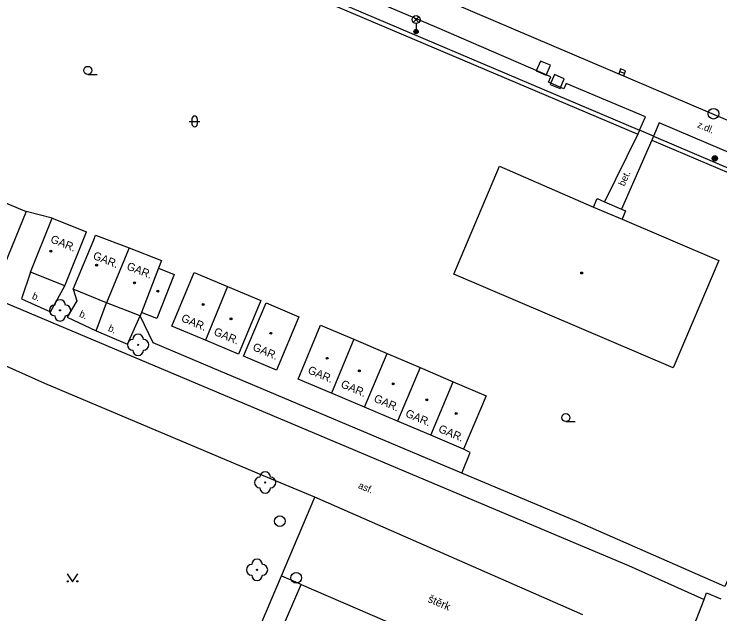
# Model space of a CAD drawing. Extents: x -596024 to -594475, y -1163820 to -1161957.
# Drawn here: x -594676 to -594609.9, y -1162309.5 to -1162253.3 of the extents above; entities that cross this region are included whole.
import ezdxf

# ---------------------------------------------------------------- set-up
doc = ezdxf.new("R2010")
doc.units = 0
for name, color, linetype in [('Level 10', 7, 'Continuous'), ('Level 11', 7, 'Continuous'), ('Level 22', 7, 'Continuous'), ('Level 25', 7, 'Continuous'), ('Level 26', 7, 'Continuous'), ('Level 27', 7, 'Continuous'), ('Level 33', 7, 'Continuous'), ('Level 36', 7, 'Continuous'), ('Level 39', 7, 'Continuous'), ('Level 40', 7, 'Continuous'), ('Level 41', 7, 'Continuous'), ('Level 5', 7, 'Continuous'), ('Level 7', 7, 'Continuous'), ('Level 8', 7, 'Continuous')]:
    doc.layers.add(name, color=color, linetype=linetype)

msp = doc.modelspace()

# ---------------------------------------------------------------- linework, layer by layer
at = {"layer": 'Level 10'}
for points in [[(-594662.38, -1162240.56), (-594636.69, -1162251.47), (-594598.02, -1162268)], [(-594682.8, -1162283.58), (-594684.03, -1162283.03), (-594686.08, -1162282.17), (-594689.66, -1162280.67), (-594687.61, -1162275.8), (-594659.66, -1162287.58)], [(-594673.15, -1162287.88), (-594682.8, -1162283.58)], [(-594652.66, -1162296.52), (-594673.15, -1162287.88)], [(-594659.66, -1162287.58), (-594623.99, -1162302.61)], [(-594647.87, -1162298.54), (-594652.66, -1162296.52)], [(-594622.76, -1162309.54), (-594647.87, -1162298.54)], [(-594623.99, -1162302.61), (-594618.49, -1162304.91), (-594611.41, -1162308.1)], [(-594611.41, -1162308.1), (-594611.18, -1162307.5), (-594609.84, -1162308.04)]]:
    msp.add_lwpolyline(points, dxfattribs=at)
at = {"layer": 'Level 11'}
for points in [[(-594625.75, -1162259.17), (-594636.44, -1162254.53), (-594664.44, -1162242.64)], [(-594625.96, -1162259.66), (-594625.75, -1162259.17)], [(-594624.53, -1162260.27), (-594625.96, -1162259.66)], [(-594624.32, -1162259.78), (-594624.53, -1162260.27)], [(-594617.44, -1162264.16), (-594616.88, -1162262.92), (-594624.32, -1162259.78)], [(-594615.6, -1162263.46), (-594616.13, -1162264.72)], [(-594598.68, -1162270.76), (-594599.02, -1162270.52), (-594615.6, -1162263.46)], [(-594617.44, -1162264.16), (-594617.62, -1162264.53)], [(-594617.62, -1162264.53), (-594620.73, -1162270.86)], [(-594616.13, -1162264.72), (-594616.29, -1162265.09)], [(-594616.29, -1162265.09), (-594619.13, -1162271.56)], [(-594621.76, -1162271.36), (-594621.42, -1162270.56), (-594620.73, -1162270.86)], [(-594620.73, -1162270.86), (-594619.13, -1162271.56)], [(-594619.13, -1162271.56), (-594618.77, -1162271.72), (-594619.09, -1162272.48)], [(-594674.48, -1162277.46), (-594675.34, -1162279.94), (-594672.62, -1162281.16), (-594671.27, -1162278.74)], [(-594670.49, -1162279.04), (-594670.15, -1162280.14), (-594671.04, -1162281.66), (-594668.34, -1162282.94)], [(-594668.34, -1162282.94), (-594667.38, -1162280.33)], [(-594668.34, -1162282.94), (-594665.4, -1162284.2), (-594664.22, -1162281.54)], [(-594650.98, -1162305.9), (-594647.87, -1162298.54)], [(-594613.33, -1162313.08), (-594611.41, -1162308.1)]]:
    msp.add_lwpolyline(points, dxfattribs=at)
at = {"layer": 'Level 22'}
for centre in [(-594671.72, -1162281.03), (-594664.41, -1162284.26), (-594652.51, -1162297.15), (-594653.27, -1162305.33)]:
    msp.add_circle(centre, 0.05, dxfattribs=at)
for centre, start, end in [((-594671.72, -1162280.53), 0, 180), ((-594672.22, -1162281.03), 90, 270), ((-594671.22, -1162281.03), 270, 90), ((-594671.72, -1162281.53), 180, 0), ((-594664.41, -1162283.76), 0, 180), ((-594664.91, -1162284.26), 90, 270), ((-594663.91, -1162284.26), 270, 90), ((-594664.41, -1162284.76), 180, 0), ((-594652.51, -1162296.65), 0, 180), ((-594653.01, -1162297.15), 90, 270), ((-594652.01, -1162297.15), 270, 90), ((-594652.51, -1162297.65), 180, 0), ((-594653.27, -1162304.83), 0, 180), ((-594653.77, -1162305.33), 90, 270), ((-594652.77, -1162305.33), 270, 90), ((-594653.27, -1162305.83), 180, 0)]:
    msp.add_arc(centre, 0.5, start, end, dxfattribs=at)
at = {"layer": 'Level 25'}
for radius in [0.25, 0.2, 0.15, 0.1, 0.05]:
    msp.add_circle((-594610.4, -1162266.8), radius, dxfattribs=at)
at = {"layer": 'Level 26'}
for points in [[(-594625.802, -1162258.081), (-594626.719, -1162257.682), (-594627.118, -1162258.599), (-594626.201, -1162258.998)], [(-594624.504, -1162259.335), (-594625.425, -1162258.944), (-594625.815, -1162259.865), (-594624.895, -1162260.256)]]:
    msp.add_lwpolyline(points, close=True, dxfattribs=at)
at = {"layer": 'Level 27'}
msp.add_line((-594619.314, -1162258.651), (-594618.846, -1162258.829), dxfattribs=at)
msp.add_lwpolyline([(-594619.402, -1162258.885), (-594618.935, -1162259.062), (-594618.758, -1162258.595), (-594619.225, -1162258.418)], close=True, dxfattribs=at)
for centre in [(-594610.52, -1162262.61), (-594651.14, -1162300.77), (-594649.6, -1162306.08)]:
    msp.add_circle(centre, 0.5, dxfattribs=at)
at = {"layer": 'Level 33'}
for p, q in [((-594638.645, -1162254.06), (-594638.115, -1162253.53)), ((-594638.645, -1162253.53), (-594638.115, -1162254.06)), ((-594638.38, -1162254.17), (-594638.38, -1162254.92))]:
    msp.add_line(p, q, dxfattribs=at)
for centre, radius in [((-594638.38, -1162253.795), 0.375), ((-594638.38, -1162254.92), 0.2), ((-594638.38, -1162254.92), 0.145), ((-594638.38, -1162254.92), 0.0876)]:
    msp.add_circle(centre, radius, dxfattribs=at)
at = {"layer": 'Level 36'}
for p, q in [((-594669.12, -1162258.925), (-594668.245, -1162258.925)), ((-594659.616, -1162263.336), (-594658.616, -1162263.336)), ((-594659.366, -1162263.086), (-594659.366, -1162263.586)), ((-594658.866, -1162263.086), (-594658.866, -1162263.586)), ((-594624.35, -1162291.445), (-594623.475, -1162291.445))]:
    msp.add_line(p, q, dxfattribs=at)
msp.add_lwpolyline([(-594671.05, -1162305.71), (-594670.55, -1162306.46), (-594670.05, -1162305.71)], dxfattribs=at)
for centre, radius in [((-594669.12, -1162258.55), 0.375), ((-594624.35, -1162291.07), 0.375), ((-594671, -1162306.41), 0.05), ((-594670.101, -1162306.41), 0.05)]:
    msp.add_circle(centre, radius, dxfattribs=at)
for centre, start, end in [((-594659.116, -1162263.086), 0, 180), ((-594659.116, -1162263.586), 180, 0)]:
    msp.add_arc(centre, 0.25, start, end, dxfattribs=at)
at = {"layer": 'Level 39'}
for centre, radius in [((-594672.59, -1162275.49), 0.09), ((-594672.59, -1162275.49), 0.0398), ((-594668.29, -1162276.8), 0.09), ((-594668.29, -1162276.8), 0.0398), ((-594622.87, -1162277.53), 0.09), ((-594622.87, -1162277.53), 0.0398), ((-594664.75, -1162278.45), 0.09), ((-594664.75, -1162278.45), 0.0398), ((-594662.57, -1162279.24), 0.09), ((-594662.57, -1162279.24), 0.0398), ((-594658.32, -1162280.49), 0.09), ((-594658.32, -1162280.49), 0.0398), ((-594655.71, -1162281.82), 0.09), ((-594655.71, -1162281.82), 0.0398), ((-594651.97, -1162283.18), 0.09), ((-594651.97, -1162283.18), 0.0398), ((-594646.71, -1162285.52), 0.09), ((-594646.71, -1162285.52), 0.0398), ((-594643.69, -1162286.69), 0.09), ((-594643.69, -1162286.69), 0.0398), ((-594640.51, -1162287.9), 0.09), ((-594640.51, -1162287.9), 0.0398), ((-594637.38, -1162289.41), 0.09), ((-594637.38, -1162289.41), 0.0398), ((-594634.62, -1162290.7), 0.09), ((-594634.62, -1162290.7), 0.0398)]:
    msp.add_circle(centre, radius, dxfattribs=at)
at = {"layer": 'Level 5'}
for points in [[(-594634.84, -1162277.63), (-594630.55, -1162267.51)], [(-594630.55, -1162267.51), (-594621.76, -1162271.36)], [(-594677.98, -1162270.5), (-594674.89, -1162271.76)], [(-594621.76, -1162271.36), (-594619.09, -1162272.48)], [(-594674.89, -1162271.76), (-594676.96, -1162276.82)], [(-594674.48, -1162277.46), (-594672.46, -1162272.38)], [(-594672.46, -1162272.38), (-594669.25, -1162273.66)], [(-594619.09, -1162272.48), (-594610.01, -1162276.35)], [(-594671.27, -1162278.74), (-594669.25, -1162273.66)], [(-594670.49, -1162279.04), (-594668.57, -1162274.42), (-594668.4, -1162274)], [(-594668.4, -1162274), (-594665.24, -1162275.18)], [(-594665.24, -1162275.18), (-594667.38, -1162280.33)], [(-594665.24, -1162275.18), (-594662.23, -1162276.35)], [(-594662.23, -1162276.35), (-594662.51, -1162277.08)], [(-594610.01, -1162276.35), (-594614.29, -1162286.42)], [(-594671.27, -1162278.74), (-594674.48, -1162277.46)], [(-594662.51, -1162277.08), (-594664.1, -1162281.24)], [(-594662.51, -1162277.08), (-594661.04, -1162277.66)], [(-594661.04, -1162277.66), (-594662.67, -1162281.8)], [(-594661.24, -1162282.51), (-594659.15, -1162277.48)], [(-594659.15, -1162277.48), (-594656.04, -1162278.79)], [(-594614.29, -1162286.42), (-594634.84, -1162277.63)], [(-594656.04, -1162278.79), (-594658.11, -1162283.82)], [(-594656.04, -1162278.79), (-594652.93, -1162280.1)], [(-594667.38, -1162280.33), (-594670.49, -1162279.04)], [(-594652.93, -1162280.1), (-594655.02, -1162285.12)], [(-594664.22, -1162281.54), (-594667.38, -1162280.33)], [(-594654.55, -1162285.31), (-594652.43, -1162280.31)], [(-594652.43, -1162280.31), (-594649.37, -1162281.65)], [(-594664.1, -1162281.24), (-594664.22, -1162281.54)], [(-594662.67, -1162281.8), (-594664.1, -1162281.24)], [(-594649.37, -1162281.65), (-594651.46, -1162286.62)], [(-594658.11, -1162283.82), (-594661.24, -1162282.51)], [(-594649.42, -1162287.48), (-594647.33, -1162282.42)], [(-594647.33, -1162282.42), (-594644.21, -1162283.74)], [(-594655.02, -1162285.12), (-594658.11, -1162283.82)], [(-594644.21, -1162283.74), (-594646.31, -1162288.8)], [(-594644.21, -1162283.74), (-594641.09, -1162285.07)], [(-594651.46, -1162286.62), (-594654.55, -1162285.31)], [(-594643.21, -1162290.11), (-594641.09, -1162285.07)], [(-594641.09, -1162285.07), (-594637.99, -1162286.39)], [(-594637.99, -1162286.39), (-594640.11, -1162291.42)], [(-594637.99, -1162286.39), (-594634.89, -1162287.71)], [(-594646.31, -1162288.8), (-594649.42, -1162287.48)], [(-594637.01, -1162292.73), (-594634.89, -1162287.71)], [(-594634.89, -1162287.71), (-594631.8, -1162289.03)], [(-594643.21, -1162290.11), (-594646.31, -1162288.8)], [(-594631.8, -1162289.03), (-594633.95, -1162294.03)], [(-594640.11, -1162291.42), (-594643.21, -1162290.11)], [(-594637.01, -1162292.73), (-594640.11, -1162291.42)], [(-594633.95, -1162294.03), (-594637.01, -1162292.73)], [(-594652.78, -1162315.18), (-594649.14, -1162306.71)], [(-594649.14, -1162306.71), (-594634.89, -1162312.85)]]:
    msp.add_lwpolyline(points, dxfattribs=at)
at = {"layer": 'Level 7'}
for points in [[(-594679.84, -1162249.56), (-594677.29, -1162247.47), (-594674.53, -1162246.12), (-594671.61, -1162245.5), (-594668.6, -1162245.38), (-594665.67, -1162245.52), (-594660.54, -1162246.23), (-594650.02, -1162250.76), (-594617.62, -1162264.53)], [(-594660.41, -1162245.9), (-594658.02, -1162246.9), (-594617.44, -1162264.16)], [(-594616.13, -1162264.72), (-594594.53, -1162273.91), (-594594.68, -1162274.28)], [(-594616.29, -1162265.09), (-594594.68, -1162274.28)], [(-594672.46, -1162272.38), (-594674.89, -1162271.76)], [(-594594.68, -1162274.28), (-594609.46, -1162306.9), (-594623.32, -1162300.81)], [(-594634.08, -1162296.27), (-594657.46, -1162286.41), (-594662.99, -1162284.08), (-594664.22, -1162281.54)], [(-594634.08, -1162296.27), (-594633.3, -1162294.34)], [(-594633.3, -1162294.34), (-594633.95, -1162294.03)], [(-594623.32, -1162300.81), (-594634.08, -1162296.27)], [(-594627.09, -1162349.06), (-594642.39, -1162342.52), (-594646.25, -1162340.87), (-594646.93, -1162340.58), (-594662.82, -1162333.79), (-594658.72, -1162324.12), (-594650.98, -1162305.9)], [(-594650.98, -1162305.9), (-594649.22, -1162306.65), (-594649.14, -1162306.71)]]:
    msp.add_lwpolyline(points, dxfattribs=at)
at = {"layer": 'Level 8'}
msp.add_lwpolyline([(-594616.13, -1162264.72), (-594617.44, -1162264.16)], dxfattribs=at)

# ---------------------------------------------------------------- texts
at = {"layer": 'Level 40'}
for s, height, rotation, p in [('z.dl.', 0.65, 336.87, (-594612.1, -1162263.87)), ('bet.', 0.65, 65.94, (-594618.87, -1162269.46)), ('b.', 0.65, 336.2, (-594674.4, -1162279.91)), ('b.', 0.65, 336.2, (-594669.98, -1162281.59)), ('b.', 0.65, 336.2, (-594667.27, -1162282.93)), ('asf.', 0.65, 337.3, (-594643.85, -1162297.66)), ('štěrk', 0.75, 337, (-594637.34, -1162308.32))]:
    msp.add_text(s, height=height, rotation=rotation, dxfattribs=at).set_placement(p)
at = {"layer": 'Level 41'}
for rotation, p in [(338.26, (-594672.68, -1162274.64)), (338.26, (-594668.7, -1162276.18)), (338.26, (-594665.54, -1162277.17)), (337, (-594660.44, -1162282.02)), (337, (-594657.39, -1162283.29)), (337, (-594653.75, -1162284.73)), (337, (-594648.58, -1162286.89)), (337, (-594645.49, -1162288.2)), (337, (-594642.4, -1162289.55)), (337, (-594639.44, -1162290.95)), (337, (-594636.35, -1162292.39))]:
    msp.add_text('GAR.', height=0.75, rotation=rotation, dxfattribs=at).set_placement(p)

doc.saveas('drawing.dxf')
